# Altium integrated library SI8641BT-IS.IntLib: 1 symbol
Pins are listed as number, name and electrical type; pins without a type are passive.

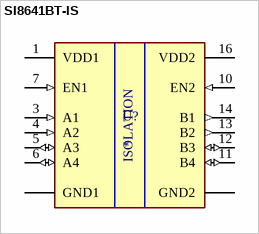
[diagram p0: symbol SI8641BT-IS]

## SI8641BT-IS
designator U?
General Purpose Digital Isolator 5000Vrms 4 Channel 150Mbps 60kV/Âµs CMTI 16-SOIC (0.295, 7.50mm Width); MP: SI8641BT-IS; MF: Silicon Labs
footprint SOIC127P1030X265-16N
pins: 1 VDD1 (power), 2 GND1 (power), 3 A1 (in), 4 A2 (in), 5 A3 (io), 6 A4 (io), 7 EN1 (in), 8 GND1 (power), 9 GND2 (power), 10 EN2 (in), 11 B4 (io), 12 B3 (io), 13 B2 (out), 14 B1 (out), 15 GND2 (power), 16 VDD2 (power)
